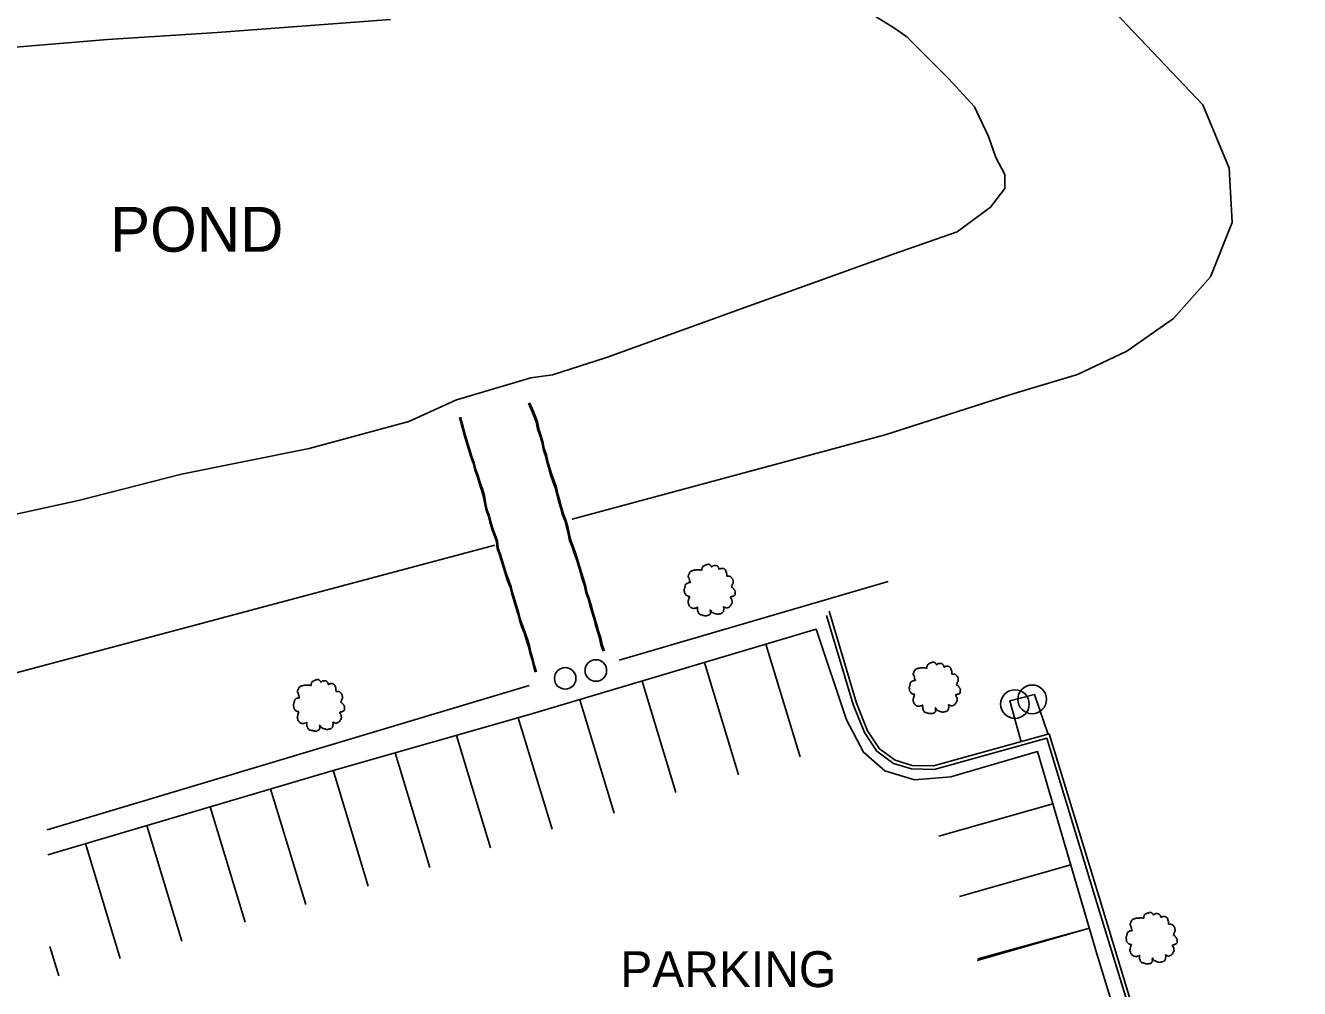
# Model space of a CAD drawing. Extents: x 1901471 to 1963503, y 756461 to 799997.
# Drawn here: x 1911829.6 to 1912007.2, y 760888.4 to 761022.6 of the extents above; entities that cross this region are included whole.
import ezdxf

# ---------------------------------------------------------------- set-up
doc = ezdxf.new("R2010")
doc.units = 0
for name, color, linetype in [('Default', 7, 'Continuous'), ('RD_EX_Conc', 7, 'Continuous'), ('RD_EX_Fence_Other', 7, 'Continuous'), ('RD_EX_GuardRail', 7, 'Continuous'), ('RD_EX_H2O', 7, 'Continuous'), ('RD_EX_Misc', 7, 'Continuous'), ('RD_EX_Road', 7, 'Continuous'), ('RD_EX_UT', 7, 'Continuous'), ('RD_EX_VEG', 7, 'Continuous'), ('RD_HC_Cl', 7, 'Continuous')]:
    doc.layers.add(name, color=color, linetype=linetype)

# ---------------------------------------------------------------- blocks, each defined once
blk = doc.blocks.new('POST')
at = {"layer": 'Default'}
for centre, start, end in [((7.776250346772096e-18, 0), 90.00000000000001, 270), ((-7.776250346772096e-18, 0), 270, 90)]:
    blk.add_arc(centre, 0.12700000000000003, start, end, dxfattribs=at)
blk = doc.blocks.new('T2')
at = {"layer": 'RD_EX_VEG'}
for points in [[(0.05233333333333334, 7.213166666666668), (-0.24750000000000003, 7.238166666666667), (-0.5723333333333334, 7.138166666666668), (-0.8222500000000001, 7.038250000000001), (-1.0471666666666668, 6.963250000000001), (-1.2720833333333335, 6.863250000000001), (-1.5719166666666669, 6.688416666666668), (-1.7968333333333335, 6.488416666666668), (-1.9218333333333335, 6.2385833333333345), (-1.9718333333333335, 6.013666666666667), (-2.0217500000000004, 5.738833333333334), (-2.0217500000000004, 5.563833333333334), (-2.146666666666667, 5.538833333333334), (-2.296666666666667, 5.563833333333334), (-2.5465000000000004, 5.638833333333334), (-2.796416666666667, 5.638833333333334), (-3.0463333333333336, 5.638833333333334), (-3.3961666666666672, 5.613833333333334), (-3.7460000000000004, 5.613833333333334), (-4.020833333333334, 5.563833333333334), (-4.345750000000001, 5.513916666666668), (-4.720583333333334, 5.389000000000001), (-5.0704166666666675, 5.264000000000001), (-5.37025, 5.014083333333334), (-5.620166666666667, 4.539333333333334), (-5.745166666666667, 4.189500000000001), (-5.895083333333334, 3.9395833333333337), (-5.745166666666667, 3.489833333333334), (-5.570166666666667, 3.139916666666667), (-5.545250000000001, 2.9400000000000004), (-5.470250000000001, 2.5152500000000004), (-5.37025, 2.2903333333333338), (-5.245333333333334, 2.0903333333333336), (-5.320250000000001, 2.065416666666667), (-5.695166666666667, 2.015416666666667), (-5.995000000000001, 1.9155000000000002), (-6.419833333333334, 1.6905833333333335), (-6.644750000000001, 1.465666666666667), (-6.744750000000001, 1.1407500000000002), (-6.769666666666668, 0.7909166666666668), (-6.869583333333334, 0.5910833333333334), (-6.944583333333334, 0.3161666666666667), (-6.969583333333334, 0.2411666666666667), (-7.019583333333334, -0.08366666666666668), (-6.9195833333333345, -0.5335000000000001), (-6.894583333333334, -0.8833333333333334), (-6.769666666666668, -1.1082500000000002), (-6.619750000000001, -1.2830833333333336), (-6.444833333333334, -1.5330000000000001), (-6.045000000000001, -1.7579166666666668), (-5.7201666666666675, -1.8579166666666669), (-5.520250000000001, -1.8828333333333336), (-5.695166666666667, -2.382666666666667), (-5.745166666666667, -2.7325000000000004), (-5.870083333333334, -3.132333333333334), (-5.870083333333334, -3.2072500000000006), (-5.920000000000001, -3.682083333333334), (-5.770166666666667, -4.007000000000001), (-5.695166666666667, -4.38175), (-5.520250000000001, -4.606666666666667), (-5.245333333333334, -4.906583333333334), (-4.9205000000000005, -5.131416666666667), (-4.420666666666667, -5.256416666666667), (-4.020833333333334, -5.231416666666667), (-3.4460833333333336, -5.056500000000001), (-3.1962500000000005, -4.9815000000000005), (-3.2212500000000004, -5.156416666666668), (-3.1962500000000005, -5.531333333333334), (-3.1962500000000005, -5.956083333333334), (-3.0463333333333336, -6.280916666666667), (-2.946333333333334, -6.555833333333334), (-2.796416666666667, -6.805750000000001), (-2.4715000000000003, -7.030583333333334), (-2.07175, -7.1055833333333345), (-1.6469166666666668, -7.2555000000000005), (-1.1970833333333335, -7.330500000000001), (-0.6973333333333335, -7.355500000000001), (-0.09758333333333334, -7.205583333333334), (0.17725000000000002, -7.080583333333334), (0.27725000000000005, -6.905666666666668), (0.47716666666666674, -6.530833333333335), (0.4271666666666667, -6.3059166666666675), (0.4521666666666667, -5.706166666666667), (0.5520833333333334, -5.881166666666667), (0.7270833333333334, -6.231000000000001), (1.2268333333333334, -6.530833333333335), (1.626666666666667, -6.705750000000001), (2.101416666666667, -6.8557500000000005), (2.4013333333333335, -6.930666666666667), (2.8760833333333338, -6.8557500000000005), (3.2510000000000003, -6.780750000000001), (3.6257500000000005, -6.655750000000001), (3.9256666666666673, -6.380916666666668), (4.100583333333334, -6.106000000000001), (4.1505833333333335, -5.831166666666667), (4.2255, -5.456333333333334), (4.275500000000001, -5.281416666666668)], [(4.275500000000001, -5.281416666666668), (4.200583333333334, -5.106416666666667), (4.1505833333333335, -4.856583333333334), (4.2255, -4.881583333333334), (4.4004166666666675, -4.931583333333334), (4.675333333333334, -5.056500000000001), (4.900250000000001, -5.131416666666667), (5.225083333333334, -5.106416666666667), (5.500000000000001, -5.006500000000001), (5.949750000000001, -4.731583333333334), (6.224666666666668, -4.256833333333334), (6.499500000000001, -3.8570000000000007), (6.5745000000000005, -3.5321666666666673), (6.524500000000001, -3.3072500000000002), (6.499500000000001, -2.8075000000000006), (6.299583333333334, -2.5575833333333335), (6.249583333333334, -2.432666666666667), (6.1496666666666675, -2.0328333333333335), (6.224666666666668, -1.9828333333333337), (6.499500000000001, -1.9328333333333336), (6.874333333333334, -1.8079166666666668), (7.149250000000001, -1.6830000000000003), (7.374166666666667, -1.5080000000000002), (7.449083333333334, -1.2830833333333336), (7.424166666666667, -0.8833333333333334), (7.4740833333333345, -0.48350000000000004), (7.399166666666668, -0.3335), (7.299166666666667, -0.1836666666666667), (7.224166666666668, 0.016333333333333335), (7.074250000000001, 0.16616666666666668), (6.974333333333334, 0.3161666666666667), (6.874333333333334, 0.41608333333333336), (6.749416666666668, 0.5660833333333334), (6.5745000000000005, 0.6910000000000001), (6.424583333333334, 0.7410000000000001), (6.374583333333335, 0.8909166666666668), (6.524500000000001, 1.0908333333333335), (6.5745000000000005, 1.1907500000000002), (6.599416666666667, 1.4156666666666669), (6.824416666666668, 1.7655000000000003), (6.874333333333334, 2.1653333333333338), (6.824416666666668, 2.590166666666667), (6.774416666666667, 2.8650833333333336), (6.624416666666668, 3.139916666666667), (6.424583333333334, 3.3898333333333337), (6.299583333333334, 3.5647500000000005), (6.124666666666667, 3.689666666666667), (5.799833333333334, 3.814666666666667), (5.549916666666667, 3.864583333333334), (5.200083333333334, 3.864583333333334), (5.000166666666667, 3.9145833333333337), (5.025166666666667, 3.964583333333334), (5.025166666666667, 4.1145000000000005), (5.025166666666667, 4.389416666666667), (4.950166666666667, 4.839166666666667), (4.800250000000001, 5.339), (4.800250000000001, 5.364000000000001), (4.7002500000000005, 5.613833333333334), (4.475416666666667, 5.813750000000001), (4.3005, 5.913666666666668), (4.100583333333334, 6.038666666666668), (3.850666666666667, 6.063666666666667), (3.5508333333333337, 6.063666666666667), (3.2759166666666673, 6.013666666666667), (3.0760000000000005, 5.913666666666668), (2.9010833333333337, 5.788750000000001), (2.8260833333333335, 5.938666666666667), (2.726166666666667, 6.2385833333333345), (2.676166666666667, 6.3885000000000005), (2.52625, 6.563416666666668), (2.301416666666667, 6.7633333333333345), (1.8515000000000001, 6.888250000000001), (1.2268333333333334, 6.813333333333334), (0.9269166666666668, 6.613416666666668), (0.7770000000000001, 6.438500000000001), (0.7270833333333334, 6.563416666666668), (0.5270833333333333, 6.7633333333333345), (0.4271666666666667, 6.938250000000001), (0.25225000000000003, 7.063250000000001), (0.10233333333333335, 7.163166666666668), (0.0023333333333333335, 7.213166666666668)]]:
    blk.add_spline(points, degree=3, dxfattribs=at)
blk = doc.blocks.new('OP')
at = {"layer": 'Default'}
for centre, start, end in [((7.776250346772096e-18, 0), 90.00000000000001, 270), ((-7.776250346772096e-18, 0), 270, 90)]:
    blk.add_arc(centre, 0.12700000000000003, start, end, dxfattribs=at)

msp = doc.modelspace()

# ---------------------------------------------------------------- linework, layer by layer
at = {"layer": 'RD_EX_Conc'}
for points in [[(1911899.7400000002, 760970.0000000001), (1911900.1200000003, 760969.1300000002), (1911900.5000000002, 760968.2500000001), (1911900.8200000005, 760967.3500000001), (1911901.0200000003, 760966.4200000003), (1911901.3100000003, 760965.5200000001), (1911901.5900000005, 760964.6100000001), (1911901.7800000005, 760963.6700000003), (1911902.0700000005, 760962.7700000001), (1911902.3000000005, 760961.8500000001), (1911902.5700000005, 760960.9300000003), (1911902.8200000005, 760960.0200000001), (1911903.14, 760959.1200000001), (1911903.4600000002, 760958.2300000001), (1911903.6800000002, 760957.3), (1911903.9300000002, 760956.3800000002), (1911904.1800000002, 760955.4700000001), (1911904.4500000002, 760954.56), (1911904.8000000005, 760953.6700000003), (1911905.0500000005, 760952.7500000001), (1911905.2700000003, 760951.83), (1911905.4700000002, 760950.8900000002), (1911905.8300000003, 760950.0100000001), (1911906.1100000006, 760949.1000000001), (1911906.4300000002, 760948.2100000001), (1911906.7100000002, 760947.3), (1911906.9900000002, 760946.3900000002), (1911907.2300000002, 760945.4700000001), (1911907.5400000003, 760944.57), (1911907.7200000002, 760943.6400000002), (1911908.0400000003, 760942.7400000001), (1911908.3100000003, 760941.83), (1911908.5700000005, 760940.9200000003), (1911908.8300000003, 760940.0000000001), (1911909.1000000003, 760939.0900000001), (1911909.3500000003, 760938.1800000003), (1911909.6300000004, 760937.2700000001), (1911909.8200000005, 760936.33), (1911910.1600000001, 760935.4400000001)], [(1911899.9000000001, 760970.05), (1911900.2800000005, 760969.1800000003), (1911900.6600000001, 760968.3), (1911900.9800000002, 760967.4000000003), (1911901.1800000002, 760966.4700000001), (1911901.4800000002, 760965.57), (1911901.7600000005, 760964.6600000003), (1911901.9400000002, 760963.7200000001), (1911902.2400000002, 760962.82), (1911902.4600000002, 760961.9000000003), (1911902.7300000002, 760960.9800000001), (1911902.9900000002, 760960.07), (1911903.3100000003, 760959.1700000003), (1911903.6300000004, 760958.2800000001), (1911903.8400000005, 760957.3500000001), (1911904.0900000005, 760956.4400000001), (1911904.3500000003, 760955.5200000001), (1911904.6200000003, 760954.6100000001), (1911904.9600000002, 760953.7200000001), (1911905.2200000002, 760952.81), (1911905.4300000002, 760951.8800000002), (1911905.6300000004, 760950.9400000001), (1911905.9900000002, 760950.06), (1911906.2700000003, 760949.1500000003), (1911906.5900000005, 760948.2600000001), (1911906.8700000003, 760947.3500000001), (1911907.1500000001, 760946.4400000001), (1911907.39, 760945.5200000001), (1911907.7000000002, 760944.6300000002), (1911907.89, 760943.6900000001), (1911908.2100000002, 760942.7900000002), (1911908.4800000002, 760941.8800000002), (1911908.7300000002, 760940.9700000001), (1911909.0000000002, 760940.05), (1911909.2600000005, 760939.1400000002), (1911909.5200000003, 760938.2300000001), (1911909.8000000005, 760937.32), (1911909.9900000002, 760936.3800000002), (1911910.3200000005, 760935.4900000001)], [(1911890.1300000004, 760968.0200000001), (1911890.8800000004, 760965.2800000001), (1911891.6900000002, 760962.5400000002), (1911892.0400000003, 760961.6600000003), (1911892.2700000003, 760960.7300000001), (1911892.5800000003, 760959.83), (1911892.8600000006, 760958.9300000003), (1911893.1600000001, 760958.0300000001), (1911893.4400000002, 760957.1200000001), (1911893.6100000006, 760956.1800000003), (1911893.8000000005, 760955.2400000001), (1911894.1000000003, 760954.3400000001), (1911894.3600000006, 760953.4300000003), (1911894.64, 760952.5200000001), (1911894.9500000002, 760951.6200000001), (1911895.2700000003, 760950.7200000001), (1911895.39, 760949.7700000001), (1911895.7100000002, 760948.8700000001), (1911895.9900000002, 760947.9600000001), (1911896.2600000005, 760947.05), (1911896.5400000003, 760946.1500000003), (1911896.8300000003, 760945.2400000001), (1911897.1900000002, 760944.3600000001), (1911897.4200000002, 760943.4300000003), (1911897.6900000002, 760942.5200000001), (1911897.9700000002, 760941.6100000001), (1911898.2400000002, 760940.7000000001), (1911898.4700000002, 760939.7800000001), (1911898.7800000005, 760938.8900000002), (1911899.14, 760938.0000000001), (1911899.4200000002, 760937.0900000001), (1911899.7000000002, 760936.1900000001), (1911899.9200000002, 760935.2600000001), (1911900.1900000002, 760934.3500000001), (1911900.4300000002, 760933.4300000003), (1911900.6800000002, 760932.5100000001)], [(1911890.2700000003, 760968.07), (1911891.0300000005, 760965.32), (1911891.8400000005, 760962.5900000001), (1911892.1800000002, 760961.7000000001), (1911892.4100000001, 760960.7800000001), (1911892.7200000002, 760959.8800000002), (1911893.0000000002, 760958.9700000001), (1911893.3100000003, 760958.07), (1911893.5900000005, 760957.1600000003), (1911893.7500000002, 760956.2200000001), (1911893.9500000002, 760955.2900000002), (1911894.2500000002, 760954.3800000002), (1911894.5100000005, 760953.4700000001), (1911894.7900000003, 760952.56), (1911895.0900000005, 760951.6600000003), (1911895.4100000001, 760950.7700000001), (1911895.5300000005, 760949.81), (1911895.8500000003, 760948.9100000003), (1911896.1300000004, 760948.0100000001), (1911896.4200000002, 760947.1000000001), (1911896.7000000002, 760946.2000000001), (1911897.0000000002, 760945.2900000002), (1911897.3500000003, 760944.4100000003), (1911897.5800000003, 760943.4800000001), (1911897.8500000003, 760942.57), (1911898.1300000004, 760941.6700000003), (1911898.4000000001, 760940.7500000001), (1911898.6300000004, 760939.83), (1911898.9500000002, 760938.9400000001), (1911899.3000000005, 760938.05), (1911899.5900000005, 760937.1400000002), (1911899.8700000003, 760936.2400000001), (1911900.0800000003, 760935.31), (1911900.3500000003, 760934.4000000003), (1911900.5900000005, 760933.4800000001), (1911900.8400000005, 760932.56)], [(1911941.2900000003, 760940.4200000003), (1911944.9900000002, 760928.0400000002), (1911946.5500000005, 760924.1300000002), (1911948.2700000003, 760921.5100000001), (1911950.6100000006, 760919.82), (1911953.1300000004, 760919.0400000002), (1911956.2600000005, 760918.9800000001), (1911971.9700000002, 760923.32), (1911978.7800000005, 760901.0100000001), (1911983.1100000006, 760886.7700000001), (1911991.1500000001, 760858.9000000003), (1912002.3800000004, 760820.0200000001), (1912006.6500000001, 760805.5900000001)], [(1911941.6300000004, 760941.0400000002), (1911945.4700000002, 760928.2000000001), (1911946.9900000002, 760924.3600000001), (1911948.64, 760921.8600000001), (1911950.8300000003, 760920.2700000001), (1911953.2100000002, 760919.5400000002), (1911956.2000000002, 760919.4800000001), (1911972.3000000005, 760923.9300000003), (1911979.2500000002, 760901.1600000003), (1911983.5800000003, 760886.9100000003), (1911991.6300000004, 760859.0400000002), (1912002.8600000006, 760820.1600000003), (1912007.1900000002, 760805.5300000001)], [(1911968.3700000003, 760922.9700000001), (1911966.8100000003, 760928.5300000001), (1911970.2700000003, 760929.4100000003), (1911972.1700000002, 760923.8600000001)]]:
    msp.add_lwpolyline(points, dxfattribs=at)
at = {"layer": 'RD_EX_Fence_Other'}
for points in [[(1911763.4000000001, 760914.3), (1911750.8400000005, 760916.2100000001), (1911744.6200000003, 760921.2600000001), (1911722.8500000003, 760995.7000000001), (1911722.8500000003, 761003.3700000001), (1911725.5700000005, 761010.56), (1911730.0400000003, 761017.56), (1911736.0700000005, 761022.81), (1911742.2900000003, 761026.6900000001), (1911899.9000000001, 761048.3600000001), (1911922.4600000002, 761050.6900000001), (1911947.9400000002, 761043.3500000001), (1911966.7300000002, 761036.2200000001), (1911977.9600000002, 761028.2300000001), (1911993.7200000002, 761011.6100000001), (1911997.39, 761002.7500000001), (1911997.8200000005, 760995.2000000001), (1911994.8000000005, 760987.6400000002), (1911989.6200000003, 760981.81), (1911983.14, 760977.2700000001), (1911976.2300000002, 760974.0300000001), (1911966.9400000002, 760971.2300000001), (1911949.4500000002, 760965.6100000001), (1911905.8300000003, 760953.8400000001)], [(1911906.0500000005, 760953.9000000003), (1911905.8300000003, 760953.8400000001)], [(1911906.0500000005, 760953.9000000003), (1911905.8300000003, 760953.8400000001)], [(1911895.0400000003, 760950.2200000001), (1911779.2100000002, 760919.32), (1911771.0500000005, 760917.1800000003), (1911767.2500000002, 760914.6000000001)]]:
    msp.add_lwpolyline(points, dxfattribs=at)
at = {"layer": 'RD_EX_GuardRail'}
for points in [[(1911912.39, 760934.2000000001), (1911949.8800000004, 760945.1600000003)], [(1911832.6600000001, 760910.56), (1911899.8400000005, 760930.6600000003)]]:
    msp.add_lwpolyline(points, dxfattribs=at)
at = {"layer": 'RD_EX_H2O'}
for points in [[(1911944.4300000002, 761026.1600000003), (1911950.7500000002, 761022.2600000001), (1911952.4500000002, 761021.05), (1911958.2400000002, 761015.32), (1911961.89, 761011.33), (1911963.8300000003, 761007.1600000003), (1911964.8700000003, 761004.2500000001), (1911966.14, 761001.8700000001), (1911966.1300000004, 760999.9200000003), (1911964.14, 760997.3400000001), (1911959.5000000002, 760993.8700000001), (1911950.5500000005, 760990.7900000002), (1911929.7400000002, 760983.32), (1911910.6100000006, 760976.3800000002), (1911903.1100000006, 760973.9500000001), (1911900.0900000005, 760973.56), (1911889.7300000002, 760970.4600000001), (1911883.0500000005, 760967.4500000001), (1911869.1900000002, 760963.7200000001), (1911851.39, 760960.1300000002), (1911837.0500000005, 760956.4600000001), (1911818.7500000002, 760952.4400000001)], [(1911828.2500000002, 761019.6300000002), (1911841.0800000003, 761020.7000000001), (1911856.3400000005, 761021.6500000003), (1911880.5300000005, 761023.4700000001)]]:
    msp.add_lwpolyline(points, dxfattribs=at)
at = {"layer": 'RD_EX_Road'}
for points in [[(1911832.7400000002, 760907.08), (1911872.5000000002, 760918.83), (1911899.9000000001, 760926.6100000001), (1911939.8100000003, 760938.5100000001), (1911944.0400000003, 760925.9100000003), (1911946.4200000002, 760921.3600000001), (1911949.4100000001, 760918.7800000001), (1911953.5400000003, 760917.5400000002), (1911958.6000000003, 760917.9500000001), (1911970.6900000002, 760921.4700000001), (1911978.9500000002, 760893.2700000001), (1911987.5200000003, 760865.2300000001), (1911995.2700000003, 760838.2200000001), (1912000.7400000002, 760819.3700000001), (1912004.9700000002, 760805.7400000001)], [(1911937.5800000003, 760920.7200000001), (1911932.8300000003, 760936.4300000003)], [(1911929.0000000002, 760918.2400000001), (1911924.2600000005, 760933.8700000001)], [(1911920.2700000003, 760915.7500000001), (1911915.5600000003, 760931.2800000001)], [(1911911.6800000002, 760912.8900000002), (1911906.9000000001, 760928.6900000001)], [(1911903.0200000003, 760910.6300000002), (1911898.3200000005, 760926.1600000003)], [(1911894.4400000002, 760908.0300000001), (1911889.6900000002, 760923.7100000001)], [(1911886.0100000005, 760905.32), (1911881.1700000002, 760921.2900000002)], [(1911877.4200000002, 760902.7300000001), (1911872.5400000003, 760918.8500000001)], [(1911868.6900000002, 760900.1700000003), (1911863.8100000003, 760916.2600000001)], [(1911860.2600000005, 760897.6800000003), (1911855.3800000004, 760913.7700000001)], [(1911972.8200000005, 760914.1900000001), (1911956.9300000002, 760909.6900000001)], [(1911851.4500000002, 760895.05), (1911846.5700000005, 760911.1600000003)], [(1911842.8600000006, 760892.6400000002), (1911838.0200000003, 760908.6400000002)], [(1911975.3200000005, 760905.6600000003), (1911959.7900000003, 760901.2600000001)], [(1911962.3500000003, 760892.56), (1911977.9000000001, 760896.8600000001), (1911962.2800000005, 760892.3400000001)], [(1911834.2800000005, 760890.2300000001), (1911833.0500000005, 760894.3)]]:
    msp.add_lwpolyline(points, dxfattribs=at)
at = {"layer": 'RD_HC_Cl'}
msp.add_arc((1905358.488046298, 771272.4106571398), 11611.5386, 290.90197060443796, 304.0171003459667, dxfattribs=at)

# ---------------------------------------------------------------- block references
at = {"layer": 'RD_EX_Misc', "xscale": 11.811023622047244, "yscale": 11.811023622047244}
for p in [(1911909.1300000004, 760932.7600000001), (1911904.8600000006, 760931.6600000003)]:
    msp.add_blockref('POST', p, dxfattribs=at)
at = {"layer": 'RD_EX_UT', "xscale": 15.748031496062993, "yscale": 15.748031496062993}
for p in [(1911969.9300000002, 760928.7400000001), (1911967.5300000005, 760928.08)]:
    msp.add_blockref('OP', p, dxfattribs=at)
at = {"layer": 'RD_EX_VEG', "xscale": 0.4921259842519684, "yscale": 0.4921259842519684}
for p in [(1911924.89, 760944.0100000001), (1911956.2500000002, 760930.3700000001), (1911870.4400000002, 760927.9500000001), (1911986.4700000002, 760895.5000000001)]:
    msp.add_blockref('T2', p, dxfattribs=at)

# ---------------------------------------------------------------- texts
at = {"layer": 'RD_EX_H2O'}
msp.add_text('POND', height=6.250000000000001, dxfattribs=at).set_placement((1911841.4400000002, 760991.1200000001))
at = {"layer": 'RD_EX_Road'}
msp.add_text('PARKING', height=5.000000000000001, dxfattribs=at).set_placement((1911912.5300000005, 760888.6400000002))

doc.saveas('drawing.dxf')
